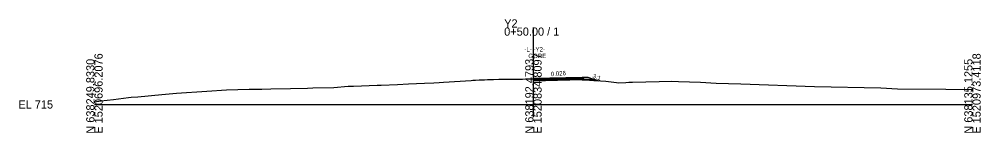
# Model space of a CAD drawing. Extents: x -26 to 1603, y -10 to 1019.
# Drawn here: x -25.7 to 302.8, y 490.3 to 529.1 of the extents above; entities that cross this region are included whole.
import ezdxf

# ---------------------------------------------------------------- set-up
doc = ezdxf.new("R2010")
doc.units = 0
for name, color, linetype in [('Exist Cross Section Cell', 7, 'Continuous'), ('Exist XS Center Line Elevation Label', 7, 'Continuous'), ('Exist XS Ground Line', 7, 'Continuous'), ('Prop CMT Pvmt Course 1', 7, 'Continuous'), ('Prop CMT Pvmt Course 2', 7, 'Continuous'), ('Prop CMT Pvmt Course 3', 7, 'Continuous'), ('Prop CMT Pvmt Surface', 7, 'Continuous'), ('Prop CMT Slope Grass', 7, 'Continuous'), ('Prop CMT Subgrade Earthwork', 7, 'Continuous'), ('Prop XS Earthwork Shape', 7, 'Continuous'), ('Prop XS Shear Point Label', 7, 'Continuous')]:
    doc.layers.add(name, color=color, linetype=linetype)

msp = doc.modelspace()

# ---------------------------------------------------------------- linework, layer by layer
at = {"layer": 'Exist Cross Section Cell'}
for p, q in [((150, 500), (150, 526.31)), ((0, 500), (150, 500)), ((150, 500), (300, 500))]:
    msp.add_line(p, q, dxfattribs=at)
at = {"layer": 'Exist XS Ground Line'}
msp.add_lwpolyline([(0, 500.92), (2.21, 501.19), (6.53, 501.72), (11.59, 502.33), (12.6, 502.44), (14.82, 502.66), (23.01, 503.45), (28.04, 503.9), (38.46, 504.59), (45.11, 505.02), (52.85, 505.19), (57.23, 505.23), (60.33, 505.29), (66.97, 505.4), (72.82, 505.55), (74.65, 505.63), (81.83, 505.81), (86.65, 506.22), (87.4, 506.23), (88.53, 506.28), (96.58, 506.58), (97.95, 506.62), (103.57, 506.77), (107.3, 507), (112.79, 507.22), (115.91, 507.34), (117.77, 507.48), (119.28, 507.58), (128.68, 508.24), (129.34, 508.27), (130.15, 508.33), (131.41, 508.39), (132.82, 508.45), (133.25, 508.47), (134.32, 508.51), (135.52, 508.55), (136.36, 508.57), (138.22, 508.6), (138.99, 508.61), (140.95, 508.63), (143.6, 508.65), (145.53, 508.69), (146.3, 508.7), (147.39, 508.72), (148.53, 508.74), (149.71, 508.77), (151.71, 508.77), (152.36, 508.76), (153.94, 508.73), (154.42, 508.72), (154.77, 508.72), (157.14, 508.68), (159.41, 508.65), (159.83, 508.64), (160.44, 508.63), (162.37, 508.6), (162.91, 508.59), (163.38, 508.6), (166.66, 508.38), (169.17, 508.29), (174.78, 507.98), (178.39, 507.45), (179.14, 507.35), (181.61, 507.55), (182.59, 507.63), (182.91, 507.66), (183.81, 507.67), (192.96, 507.81), (197.06, 507.94), (199.51, 507.89), (207.06, 507.66), (212.38, 507.33), (220.88, 507.06), (246.01, 506.17), (268.75, 505.64), (274.36, 505.33), (290.9, 505.19), (300, 505.1)], dxfattribs=at)
at = {"layer": 'Prop CMT Pvmt Course 1'}
msp.add_line((150, 508.94), (166.62, 509.37), dxfattribs=at)
at = {"layer": 'Prop CMT Pvmt Course 2'}
for p, q in [((162.62, 508.44), (162.62, 509.27)), ((150, 508.69), (166.86, 509.13))]:
    msp.add_line(p, q, dxfattribs=at)
at = {"layer": 'Prop CMT Pvmt Course 3'}
msp.add_line((150, 508.36), (167.19, 508.81), dxfattribs=at)
at = {"layer": 'Prop CMT Pvmt Surface'}
msp.add_line((150, 508.94), (166.62, 509.37), dxfattribs=at)
at = {"layer": 'Prop CMT Slope Grass'}
for p, q in [((166.62, 509.37), (168.62, 509.3)), ((168.62, 509.3), (172.16, 508.12)), ((150, 508.94), (150, 508.11)), ((150, 508.94), (150, 508.77))]:
    msp.add_line(p, q, dxfattribs=at)
at = {"layer": 'Prop CMT Subgrade Earthwork'}
for p, q in [((166.62, 509.37), (167.43, 508.56)), ((150, 508.11), (150, 508.94)), ((150, 508.11), (170.59, 508.65))]:
    msp.add_line(p, q, dxfattribs=at)
at = {"layer": 'Prop XS Earthwork Shape'}
for points in [[(150, 508.11), (164.91, 508.5), (163.38, 508.6), (162.91, 508.59), (162.37, 508.6), (160.44, 508.63), (159.83, 508.64), (159.41, 508.65), (157.14, 508.68), (154.77, 508.72), (154.42, 508.72), (153.94, 508.73), (152.36, 508.76), (151.71, 508.77), (150, 508.77)], [(169.17, 508.29), (172.16, 508.12), (170.59, 508.65), (167.43, 508.56), (164.91, 508.5), (166.66, 508.38)]]:
    msp.add_lwpolyline(points, close=True, dxfattribs=at)
at = {"layer": 'Prop XS Shear Point Label'}
msp.add_line((150, 495.67), (150, 515.27), dxfattribs=at)

# ---------------------------------------------------------------- texts
at = {"layer": 'Exist Cross Section Cell'}
for s, p in [('Y2', (140, 526.31)), ('0+50.00 / 1', (140, 523.51)), ('EL 715', (-26, 498.6))]:
    msp.add_text(s, height=2.8, dxfattribs=at).set_placement(p)
for s, p in [('E 1520696.2076', (2.8, 490)), ('E 1520834.8097', (152.8, 490)), ('E 1520973.4118', (302.8, 490)), ('N 638249.8330', (0, 490)), ('N 638192.4793', (150, 490)), ('N 638135.1255', (300, 490))]:
    msp.add_text(s, height=2.8, rotation=90, dxfattribs=at).set_placement(p)
at = {"layer": 'Exist XS Center Line Elevation Label'}
for s, p in [('-L- -Y2-', (146.91, 518.1)), ('GORE', (148.26, 515.85))]:
    msp.add_text(s, height=1.5, dxfattribs=at).set_placement(p)
for s, rotation, p in [('0.026', 4.4104, (155.99, 509.63)), ('3:1', 340.1643, (170.06, 509.15))]:
    msp.add_text(s, height=1.5, rotation=rotation, dxfattribs=at).set_placement(p)

doc.saveas('drawing.dxf')
